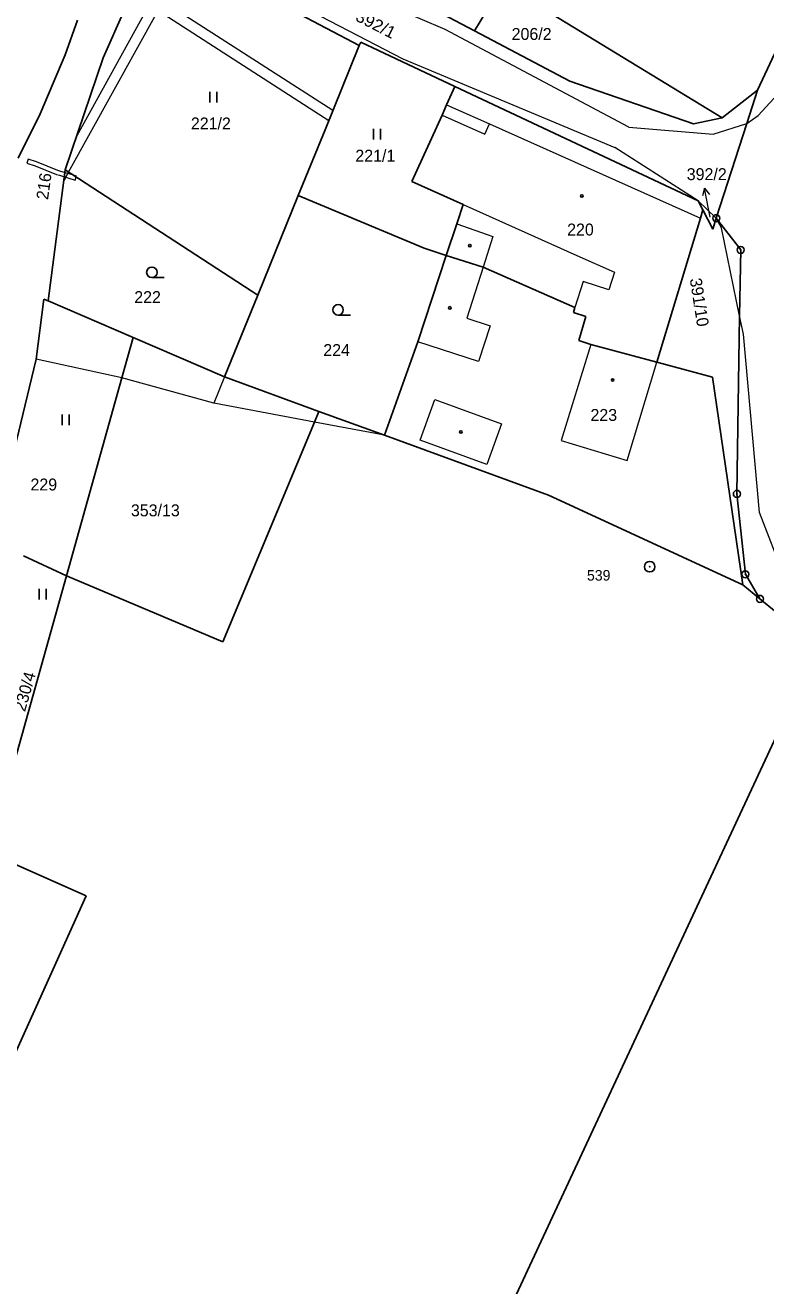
# Model space of a CAD drawing. Extents: x -504006 to -501322, y -1128098 to -1124665.
# Drawn here: x -502657.9 to -502552.5, y -1127003.9 to -1126824.4 of the extents above; entities that cross this region are included whole.
import ezdxf
from ezdxf.enums import TextEntityAlignment as Align

# ---------------------------------------------------------------- set-up
doc = ezdxf.new("R2010")
doc.units = 0
doc.header["$LTSCALE"] = 0.68
for name, color, linetype, lineweight in [('1', 7, 'Continuous', 25), ('13', 7, 'Continuous', 13), ('3', 7, 'Continuous', 25), ('4', 7, 'Continuous', 13), ('5', 7, 'Continuous', 25), ('7', 7, 'Continuous', 13), ('8', 7, 'Continuous', 25)]:
    doc.layers.add(name, color=color, linetype=linetype, lineweight=lineweight)
doc.layers.add('2', color=7, linetype='Continuous')

msp = doc.modelspace()

# ---------------------------------------------------------------- linework, layer by layer
at = {"layer": '1'}
for p, q in [((-502593.99, -1126825.19), (-502606.73, -1126818.47)), ((-502643.86, -1126822.29), (-502646.85, -1126829.07)), ((-502610.4, -1126827.3), (-502619.79, -1126822.36)), ((-502548.07, -1126821.6), (-502553.7, -1126833.67)), ((-502650.47, -1126823.67), (-502652.24, -1126828.61)), ((-502580.43, -1126832.35), (-502593.99, -1126825.19)), ((-502615.26, -1126839.31), (-502610.4, -1126827.3)), ((-502610.4, -1126827.3), (-502610.18, -1126826.81)), ((-502610.18, -1126826.81), (-502596.76, -1126833.13)), ((-502652.24, -1126828.61), (-502655.79, -1126837.04)), ((-502646.85, -1126829.07), (-502652.25, -1126844.99)), ((-502597.95, -1126835.75), (-502596.76, -1126833.13)), ((-502562.13, -1126849.42), (-502596.76, -1126833.13)), ((-502562.83, -1126838.44), (-502580.43, -1126832.35)), ((-502553.7, -1126833.67), (-502558.71, -1126837.57)), ((-502553.7, -1126833.67), (-502555.22, -1126838.38)), ((-502598.6, -1126837.21), (-502597.95, -1126835.75)), ((-502655.79, -1126837.04), (-502658.93, -1126843.34)), ((-502602.88, -1126846.66), (-502598.6, -1126837.21)), ((-502558.71, -1126837.57), (-502562.83, -1126838.44)), ((-502555.22, -1126838.38), (-502559.57, -1126851.88)), ((-502615.26, -1126839.31), (-502619.06, -1126848.66)), ((-502652.25, -1126844.99), (-502654.69, -1126863.66)), ((-502624.83, -1126862.84), (-502652.25, -1126844.99)), ((-502595.61, -1126849.92), (-502602.88, -1126846.66)), ((-502619.06, -1126848.66), (-502624.83, -1126862.84)), ((-502619.06, -1126848.66), (-502601.17, -1126856.15)), ((-502596.52, -1126852.67), (-502595.61, -1126849.92)), ((-502561.47, -1126850.7), (-502562.13, -1126849.42)), ((-502559.57, -1126851.88), (-502562.13, -1126849.42)), ((-502561.47, -1126850.7), (-502561.83, -1126851.88)), ((-502560.07, -1126853.43), (-502561.47, -1126850.7)), ((-502598, -1126857.17), (-502596.52, -1126852.67)), ((-502561.83, -1126851.88), (-502568.03, -1126872.37)), ((-502559.57, -1126851.88), (-502560.07, -1126853.43)), ((-502556.09, -1126856.4), (-502559.57, -1126851.88)), ((-502598, -1126857.17), (-502601.17, -1126856.15)), ((-502556.24, -1126865.77), (-502556.09, -1126856.4)), ((-502602.06, -1126869.5), (-502598, -1126857.17)), ((-502592.75, -1126858.86), (-502598, -1126857.17)), ((-502579.68, -1126864.61), (-502592.75, -1126858.86)), ((-502656.38, -1126871.93), (-502655.3, -1126863.4)), ((-502654.69, -1126863.66), (-502655.3, -1126863.4)), ((-502642.56, -1126868.87), (-502654.69, -1126863.66)), ((-502624.83, -1126862.84), (-502629.56, -1126874.46)), ((-502579.9, -1126865.31), (-502579.68, -1126864.61)), ((-502578.14, -1126865.88), (-502579.9, -1126865.31)), ((-502579.11, -1126869.31), (-502578.14, -1126865.88)), ((-502556.63, -1126891.13), (-502556.24, -1126865.77)), ((-502642.56, -1126868.87), (-502644.17, -1126874.6)), ((-502642.56, -1126868.87), (-502629.56, -1126874.46)), ((-502606.79, -1126882.79), (-502602.06, -1126869.5)), ((-502577.44, -1126869.84), (-502579.11, -1126869.31)), ((-502568.03, -1126872.37), (-502577.44, -1126869.84)), ((-502656.38, -1126871.93), (-502662.64, -1126897.84)), ((-502568.03, -1126872.37), (-502560.11, -1126874.5)), ((-502644.17, -1126874.6), (-502652.07, -1126902.81)), ((-502616.12, -1126879.38), (-502629.56, -1126874.46)), ((-502560.11, -1126874.5), (-502555.77, -1126904.09)), ((-502616.12, -1126879.38), (-502616.76, -1126880.94)), ((-502606.79, -1126882.79), (-502616.12, -1126879.38)), ((-502616.76, -1126880.94), (-502629.8, -1126912.19)), ((-502583.44, -1126891.31), (-502606.79, -1126882.79)), ((-502555.77, -1126904.09), (-502583.44, -1126891.31)), ((-502555.43, -1126902.58), (-502556.63, -1126891.13)), ((-502658.16, -1126899.95), (-502652.07, -1126902.81)), ((-502652.07, -1126902.81), (-502662.54, -1126940.17)), ((-502629.8, -1126912.19), (-502652.07, -1126902.81)), ((-502553.35, -1126906.08), (-502555.43, -1126902.58)), ((-502553.35, -1126906.08), (-502555.77, -1126904.09)), ((-502548.72, -1126909.88), (-502553.35, -1126906.08)), ((-502546.27, -1126915.37), (-502588.67, -1127006.49)), ((-502663.54, -1126942), (-502649.24, -1126948.37)), ((-502649.24, -1126948.37), (-502663.72, -1126980.38))]:
    msp.add_line(p, q, dxfattribs=at)
msp.add_lwpolyline([(-502593.99, -1126825.19), (-502589.96, -1126818.51), (-502558.71, -1126837.57)], dxfattribs=at)
at = {"layer": '13'}
for points in [[(-502614.72, -1126837.98), (-502614.15, -1126836.57), (-502639.56, -1126820.18), (-502650.61, -1126840.15), (-502652.25, -1126844.99), (-502652.46, -1126846.59), (-502651.75, -1126845.32), (-502639.03, -1126822.31)], [(-502657.52, -1126843.47), (-502657.71, -1126844.04), (-502656.54, -1126844.43), (-502653.49, -1126845.64), (-502653.06, -1126845.77), (-502650.82, -1126846.46), (-502650.69, -1126846.01), (-502650.65, -1126845.88), (-502651.08, -1126845.75), (-502652.99, -1126845.17), (-502653.29, -1126845.08), (-502656.34, -1126843.87)]]:
    msp.add_lwpolyline(points, close=True, dxfattribs=at)
at = {"layer": '3'}
for p, q in [((-502631.671, -1126835.41), (-502631.671, -1126833.91)), ((-502630.67, -1126835.41), (-502630.67, -1126833.91)), ((-502608.371, -1126840.66), (-502608.371, -1126839.16)), ((-502607.37, -1126840.66), (-502607.37, -1126839.16)), ((-502639.903, -1126860.34), (-502638.153, -1126860.34)), ((-502613.403, -1126865.68), (-502611.653, -1126865.68)), ((-502652.691, -1126881.34), (-502652.691, -1126879.84)), ((-502651.69, -1126881.34), (-502651.69, -1126879.84)), ((-502655.931, -1126906.15), (-502655.931, -1126904.65)), ((-502654.93, -1126906.15), (-502654.93, -1126904.65))]:
    msp.add_line(p, q, dxfattribs=at)
for centre in [(-502639.9029, -1126859.5898), (-502613.4029, -1126864.9298)]:
    msp.add_circle(centre, 0.75, dxfattribs=at)
at = {"layer": '4'}
for p, q in [((-502598.18, -1126825), (-502620.1, -1126815.6)), ((-502623.4, -1126819.2), (-502604.2, -1126829.2)), ((-502572, -1126838.9), (-502598.18, -1126825)), ((-502604.2, -1126829.2), (-502574, -1126841.8)), ((-502553.6, -1126837.25), (-502549.15, -1126832.4)), ((-502597.95, -1126835.75), (-502591.87, -1126838.47)), ((-502598.6, -1126837.21), (-502592.52, -1126839.92)), ((-502592.52, -1126839.92), (-502591.87, -1126838.47)), ((-502591.87, -1126838.47), (-502561.83, -1126851.88)), ((-502559.99, -1126839.9), (-502555.22, -1126838.38)), ((-502555.22, -1126838.38), (-502553.6, -1126837.25)), ((-502572, -1126838.9), (-502559.99, -1126839.9)), ((-502562.13, -1126849.42), (-502574, -1126841.8)), ((-502595.61, -1126849.92), (-502579.42, -1126857.17)), ((-502596.52, -1126852.67), (-502591.35, -1126854.51)), ((-502558.8, -1126853.23), (-502559.57, -1126851.88)), ((-502591.35, -1126854.51), (-502592.75, -1126858.86)), ((-502556.24, -1126865.77), (-502558.8, -1126853.23)), ((-502579.42, -1126857.17), (-502574.07, -1126859.57)), ((-502592.75, -1126858.86), (-502595.09, -1126866.11)), ((-502574.07, -1126859.57), (-502574.86, -1126862.07)), ((-502578.51, -1126860.91), (-502579.68, -1126864.61)), ((-502574.86, -1126862.07), (-502578.51, -1126860.91)), ((-502595.09, -1126866.11), (-502591.76, -1126867.19)), ((-502591.76, -1126867.19), (-502593.42, -1126872.3)), ((-502555.7, -1126868.4), (-502556.24, -1126865.77)), ((-502553.4, -1126893.8), (-502555.7, -1126868.4)), ((-502593.42, -1126872.3), (-502602.06, -1126869.5)), ((-502577.44, -1126869.84), (-502581.63, -1126883.51)), ((-502644.17, -1126874.6), (-502656.38, -1126871.93)), ((-502572.26, -1126886.36), (-502568.03, -1126872.37)), ((-502631.08, -1126878.2), (-502644.17, -1126874.6)), ((-502629.56, -1126874.46), (-502631.08, -1126878.2)), ((-502601.72, -1126883.47), (-502599.61, -1126877.7)), ((-502599.61, -1126877.7), (-502590.12, -1126881.16)), ((-502616.76, -1126880.94), (-502631.08, -1126878.2)), ((-502606.79, -1126882.79), (-502616.76, -1126880.94)), ((-502590.12, -1126881.16), (-502592.23, -1126886.93)), ((-502592.23, -1126886.93), (-502601.72, -1126883.47)), ((-502581.63, -1126883.51), (-502572.26, -1126886.36)), ((-502549.85, -1126903), (-502553.4, -1126893.8))]:
    msp.add_line(p, q, dxfattribs=at)
at = {"layer": '5'}
for centre in [(-502578.7068, -1126848.7192), (-502594.6468, -1126855.7892), (-502597.4968, -1126864.6492), (-502574.3268, -1126874.9192), (-502595.9268, -1126882.3092)]:
    msp.add_circle(centre, 0.175, dxfattribs=at)
at = {"layer": '7'}
msp.add_line((-502561.233, -1126847.614), (-502561.533, -1126848.693), dxfattribs=at)
msp.add_lwpolyline([(-502560.44, -1126851.72), (-502560.66, -1126850.56), (-502561.233, -1126847.614), (-502560.55, -1126848.502)], dxfattribs=at)
at = {"layer": '8'}
for centre, radius in [((-502559.57, -1126851.8799), 0.5), ((-502559.57, -1126851.8799), 0.0303), ((-502556.09, -1126856.3999), 0.5), ((-502556.09, -1126856.3999), 0.0303), ((-502556.63, -1126891.1299), 0.5), ((-502556.63, -1126891.1299), 0.0303), ((-502569.04, -1126901.4998), 0.75), ((-502569.04, -1126901.4998), 0.03), ((-502555.43, -1126902.5799), 0.5), ((-502555.43, -1126902.5799), 0.0303), ((-502553.35, -1126906.0799), 0.5), ((-502553.35, -1126906.0799), 0.0303)]:
    msp.add_circle(centre, radius, dxfattribs=at)

# ---------------------------------------------------------------- texts
at = {"layer": '2', "width": 1.05}
msp.add_text('392/1', height=1.7, rotation=333, dxfattribs=at).set_placement((-502611.062, -1126823.678))
at = {"layer": '2'}
for s, p in [('206/2', (-502585.85, -1126826.505)), ('221/2', (-502631.51, -1126839.245)), ('221/1', (-502608.1, -1126843.835)), ('220', (-502578.899, -1126854.345)), ('222', (-502640.519, -1126863.965)), ('224', (-502613.609, -1126871.505)), ('223', (-502575.579, -1126880.745)), ('229', (-502655.289, -1126890.645))]:
    msp.add_text(s, height=1.7, dxfattribs=at).set_placement(p, align=Align.CENTER)
for s, rotation, p in [('216', 82, (-502654.4304, -1126847.4483)), ('230/4', 74, (-502657.1871, -1126919.4978))]:
    msp.add_text(s, height=1.7, rotation=rotation, dxfattribs=at).set_placement(p, align=Align.CENTER)
msp.add_text('392/2', height=1.7, dxfattribs=at).set_placement((-502558.08, -1126846.465), align=Align.RIGHT)
msp.add_text('391/10', height=1.7, rotation=279, dxfattribs=at).set_placement((-502563.349, -1126860.546))
msp.add_text('353/13', height=1.7, dxfattribs=at).set_placement((-502642.89, -1126894.325))
at = {"layer": '8'}
msp.add_text('539', height=1.5, dxfattribs=at).set_placement((-502574.629, -1126903.475), align=Align.RIGHT)

doc.saveas('drawing.dxf')
